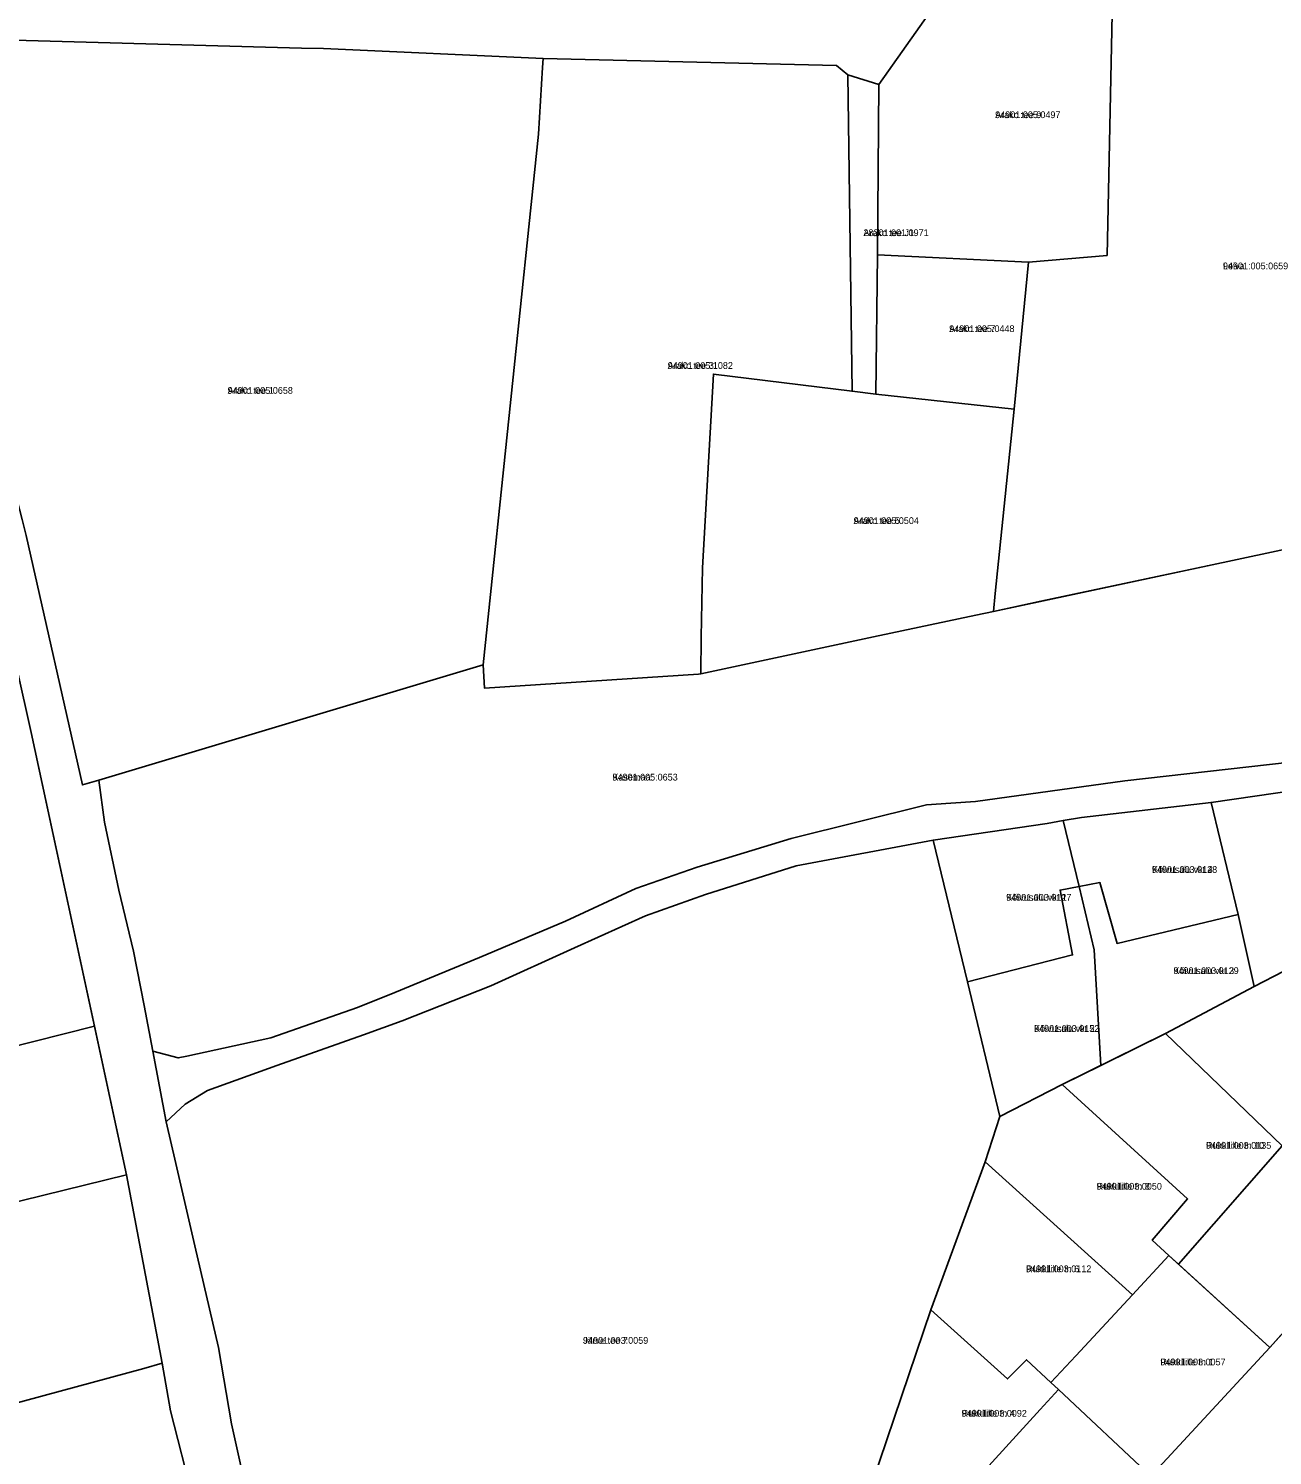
# Model space of a CAD drawing. Extents: x 647845 to 668483, y 6445298 to 6473683.
# Drawn here: x 652826.7 to 653103.1, y 6468125.6 to 6468442.7 of the extents above; entities that cross this region are included whole.
import ezdxf

# ---------------------------------------------------------------- set-up
doc = ezdxf.new("R2010")
doc.units = 0
for name, color, linetype in [('L_AADRESS', 7, 'Continuous'), ('PIIR', 7, 'Continuous'), ('TUNNUS', 7, 'Continuous')]:
    doc.layers.add(name, color=color, linetype=linetype)

msp = doc.modelspace()

# ---------------------------------------------------------------- linework, layer by layer
at = {"layer": 'PIIR'}
for points in [[(653087.15, 6468455.12), (653106.19, 6468452.12), (653126.25, 6468450.45), (653141.05, 6468449.59), (653142.85, 6468409), (653140.61, 6468376.44), (653143.13, 6468374.95), (653143.07, 6468373.88), (653142.39, 6468357.49), (653141.94, 6468346.77), (653141.8, 6468343.37), (653141.18, 6468340.19), (653140.59, 6468337.22), (653138.12, 6468335.41), (653131.32, 6468332.4), (653088.65, 6468323.31), (653051.67, 6468315.43), (653041.08, 6468313.17), (653041.5, 6468317.18), (653045.72, 6468358.09), (653048.9, 6468390.78), (653066.36, 6468392.28), (653067.62, 6468453.16), (653067.74, 6468456.41)], [(653066.36, 6468392.28), (653048.9, 6468390.78), (653015.37, 6468392.4), (653015.66, 6468430.26), (653032.96, 6468454.83), (653067.62, 6468453.16)], [(652810.15, 6468440.46), (652887.33, 6468438.3), (652892.24, 6468438.27), (652941, 6468436.05), (652940.88, 6468434.02), (652940.02, 6468419.18), (652927.71, 6468301.3), (652842.29, 6468275.7), (652838.61, 6468274.61), (652826.09, 6468330.06), (652825.23, 6468333.58), (652811.23, 6468387.58), (652801.01, 6468421.51), (652800.8, 6468423.5), (652803.12, 6468427.72), (652808.72, 6468437.86)], [(653006.24, 6468434.44), (653008.74, 6468432.39), (653009.69, 6468362.1), (652978.88, 6468365.9), (652976.42, 6468322.83), (652976.11, 6468307.47), (652976.04, 6468299.31), (652975.52, 6468299.2), (652928.01, 6468296.08), (652927.71, 6468301.3), (652940.02, 6468419.18), (652940.88, 6468434.02), (652941, 6468436.05)], [(653015.37, 6468392.4), (653015, 6468361.45), (653009.69, 6468362.1), (653008.74, 6468432.39), (653015.66, 6468430.26)], [(653045.72, 6468358.09), (653015, 6468361.45), (653015.37, 6468392.4), (653048.9, 6468390.78)], [(653045.72, 6468358.09), (653041.5, 6468317.18), (653041.08, 6468313.17), (653037.22, 6468312.35), (653014.41, 6468307.49), (653007.19, 6468305.95), (652976.04, 6468299.31), (652976.11, 6468307.47), (652976.42, 6468322.83), (652978.88, 6468365.9), (653009.69, 6468362.1), (653015, 6468361.45)], [(653108.88, 6468273.5), (653117.53, 6468238.89), (653115.2, 6468237.74), (653111.23, 6468236.99), (653105.63, 6468233.25), (653099.07, 6468229.79), (653095.48, 6468245.8), (653089.47, 6468270.74)], [(653060.67, 6468267.37), (653089.47, 6468270.74), (653095.48, 6468245.8), (653068.57, 6468239.41), (653064.76, 6468252.9), (653060.14, 6468252.03), (653056.62, 6468266.7)], [(653053.06, 6468266.06), (653056.62, 6468266.7), (653060.14, 6468252.03), (653055.9, 6468251.23), (653058.7, 6468236.84), (653035.31, 6468230.83), (653027.73, 6468262.36)], [(653159.55, 6468255.25), (653155.18, 6468250.32), (653127.94, 6468219.57), (653105.24, 6468194.42), (653079.36, 6468219.39), (653099.07, 6468229.79), (653105.63, 6468233.25), (653111.23, 6468236.99), (653115.2, 6468237.74), (653117.53, 6468238.89), (653121.97, 6468241.09), (653139.46, 6468249.71), (653149.66, 6468254.73), (653156.84, 6468258.27)], [(653064.76, 6468252.9), (653068.57, 6468239.41), (653095.48, 6468245.8), (653099.07, 6468229.79), (653079.36, 6468219.39), (653064.95, 6468212.29), (653063.48, 6468237.97), (653060.14, 6468252.03)], [(653035.31, 6468230.83), (653058.7, 6468236.84), (653055.9, 6468251.23), (653060.14, 6468252.03), (653063.48, 6468237.97), (653064.95, 6468212.29), (653056.37, 6468208.06), (653042.5, 6468200.92)], [(652708.05, 6468164.62), (652668.02, 6468177.22), (652841.34, 6468221.01), (652848.45, 6468187.96), (652728.2, 6468158.42)], [(653076.39, 6468173.43), (653084.24, 6468182.61), (653056.37, 6468208.06), (653079.36, 6468219.39), (653105.24, 6468194.42), (653082.22, 6468168.12), (653080.11, 6468170.05)], [(653042.5, 6468200.92), (653056.37, 6468208.06), (653084.24, 6468182.61), (653076.39, 6468173.43), (653080.11, 6468170.05), (653071.99, 6468161.31), (653039.28, 6468190.86)], [(653082.22, 6468168.12), (653105.24, 6468194.42), (653125.06, 6468175.07), (653111.91, 6468159.99), (653129.22, 6468144.14), (653132.9, 6468140.76), (653130.64, 6468137.01), (653126.55, 6468140.66), (653108.78, 6468156.49), (653102.5, 6468149.63)], [(653048.46, 6468146.9), (653044.19, 6468142.63), (653027.19, 6468157.96), (653039.28, 6468190.86), (653071.99, 6468161.31), (653059.42, 6468147.77), (653053.89, 6468141.82)], [(652728.2, 6468158.42), (652848.45, 6468187.96), (652856.38, 6468146.12), (652852.26, 6468144.93), (652788.49, 6468127.7), (652750.15, 6468133.39)], [(653059.42, 6468147.77), (653071.99, 6468161.31), (653080.11, 6468170.05), (653102.5, 6468149.63), (653078.78, 6468123.92), (653076.11, 6468121.03), (653055.56, 6468140.26), (653053.89, 6468141.82)], [(653053.89, 6468141.82), (653055.56, 6468140.26), (653051.5, 6468135.82), (653030.87, 6468113.23), (653024.23, 6468106.41), (653012.5, 6468114.64), (653027.19, 6468157.96), (653044.19, 6468142.63), (653048.46, 6468146.9)], [(653108.76, 6468156.54), (653126.5, 6468140.67), (653130.64, 6468137.01), (653119.41, 6468124.87), (653097.41, 6468101.09), (653077.36, 6468119.85), (653076.11, 6468121.03), (653078.78, 6468123.92), (653102.5, 6468149.63)], [(652852.26, 6468144.93), (652856.38, 6468146.12), (652858.19, 6468135.57), (652863.15, 6468116.11), (652866.02, 6468104.67), (652868.33, 6468095.86), (652865.88, 6468090.16), (652831.1, 6468071.11), (652788.49, 6468127.7)], [(653055.56, 6468140.26), (653076.11, 6468121.03), (653077.36, 6468119.85), (653073.77, 6468116.32), (653052.66, 6468093.31), (653030.87, 6468113.23), (653051.5, 6468135.82)]]:
    msp.add_lwpolyline(points, close=True, dxfattribs=at)
for points in [[(653032.96, 6468454.83), (653015.66, 6468430.26), (653008.74, 6468432.39), (653006.24, 6468434.44), (652941, 6468436.05), (652892.24, 6468438.27), (652887.33, 6468438.3), (652810.15, 6468440.46), (652808.72, 6468437.86), (652803.12, 6468427.72), (652800.8, 6468423.5), (652798.4, 6468427.73), (652787.68, 6468441.64), (652775.05, 6468447.96)], [(653134.64, 6468282.77), (653070.29, 6468275.56), (653037.1, 6468270.93), (653031.65, 6468270.55), (653026.19, 6468270.16), (652996.13, 6468262.72), (652975.28, 6468256.34), (652961.66, 6468251.61), (652946, 6468244.36), (652926.86, 6468236.28), (652908.06, 6468228.5), (652899.74, 6468225.18), (652880.47, 6468218.43), (652861.82, 6468214.33), (652859.92, 6468213.96), (652854.28, 6468215.46), (652852.34, 6468225.61), (652849.99, 6468237.71), (652846.69, 6468251.24), (652843.57, 6468266.31), (652842.29, 6468275.7), (652927.71, 6468301.3), (652928.01, 6468296.08), (652975.52, 6468299.2), (652976.04, 6468299.31), (653007.19, 6468305.95), (653014.41, 6468307.49), (653037.22, 6468312.35), (653041.08, 6468313.17), (653088.65, 6468323.31), (653131.32, 6468332.4)], [(652826.09, 6468330.06), (652838.61, 6468274.61), (652842.29, 6468275.7), (652843.57, 6468266.31), (652846.69, 6468251.24), (652849.99, 6468237.71), (652852.34, 6468225.61), (652854.28, 6468215.46), (652857.26, 6468199.76), (652859.4, 6468190.49), (652863.63, 6468172.17), (652868.86, 6468149.63), (652871.74, 6468132.65), (652874.72, 6468119.35)], [(652820.98, 6468314.16), (652827.25, 6468286.23), (652841.34, 6468221.01), (652668.02, 6468177.22)], [(652863.15, 6468116.11), (652858.19, 6468135.57), (652856.38, 6468146.12), (652848.45, 6468187.96), (652827.25, 6468286.23), (652820.98, 6468314.16)], [(653108.88, 6468273.5), (653089.47, 6468270.74), (653060.67, 6468267.37), (653056.62, 6468266.7), (653053.06, 6468266.06), (653027.73, 6468262.36), (652997.29, 6468256.61), (652977.12, 6468250.29), (652963.78, 6468245.54), (652947.96, 6468238.42), (652929.37, 6468229.98), (652909.69, 6468222.2), (652901.13, 6468219.05), (652881.8, 6468212.26), (652866.46, 6468206.75), (652861.44, 6468203.67), (652857.26, 6468199.76), (652854.28, 6468215.46), (652859.92, 6468213.96), (652861.82, 6468214.33), (652880.47, 6468218.43), (652899.74, 6468225.18), (652908.06, 6468228.5), (652926.86, 6468236.28), (652946, 6468244.36), (652961.66, 6468251.61), (652975.28, 6468256.34), (652996.13, 6468262.72), (653026.19, 6468270.16), (653031.65, 6468270.55), (653037.1, 6468270.93), (653070.29, 6468275.56), (653134.64, 6468282.77)], [(652874.72, 6468119.35), (652871.74, 6468132.65), (652868.86, 6468149.63), (652863.63, 6468172.17), (652859.4, 6468190.49), (652857.26, 6468199.76), (652861.44, 6468203.67), (652866.46, 6468206.75), (652881.8, 6468212.26), (652901.13, 6468219.05), (652909.69, 6468222.2), (652929.37, 6468229.98), (652947.96, 6468238.42), (652963.78, 6468245.54), (652977.12, 6468250.29), (652997.29, 6468256.61), (653027.73, 6468262.36), (653035.31, 6468230.83), (653042.5, 6468200.92), (653039.28, 6468190.86), (653027.19, 6468157.96), (653012.5, 6468114.64)]]:
    msp.add_lwpolyline(points, dxfattribs=at)

# ---------------------------------------------------------------- texts
at = {"layer": 'L_AADRESS'}
for s, p in [('Arako tee 9', (653041.49, 6468422.78)), ('Arako tee J1', (653012.2, 6468396.56)), ('Leiva', (653092.11, 6468389.19)), ('Arako tee 7', (653031.28, 6468375.24)), ('Arako tee 3', (652968.7, 6468367.06)), ('Arako tee 1', (652870.9, 6468361.52)), ('Arako tee 5', (653010.03, 6468332.6)), ('Kasemaa', (652956.43, 6468275.59)), ('Kõivusalu vkt 4', (653076.33, 6468255.07)), ('Kõivusalu vkt 1', (653043.93, 6468248.89)), ('Kõivusalu vkt 3', (653081.11, 6468232.59)), ('Kõivusalu vkt 2', (653050.13, 6468219.74)), ('Rukkilille tn 10', (653088.35, 6468193.76)), ('Rukkilille tn 8', (653064.04, 6468184.68)), ('Rukkilille tn 6', (653048.35, 6468166.34)), ('Järve tee 7', (652949.88, 6468150.43)), ('Rukkilille tn 1', (653078.2, 6468145.64)), ('Rukkilille tn 4', (653034.03, 6468134.24))]:
    msp.add_text(s, height=1.5, dxfattribs=at).set_placement(p)
at = {"layer": 'TUNNUS'}
for s, p in [('94901:005:0497', (653041.49, 6468422.78)), ('28301:001:0971', (653012.2, 6468396.56)), ('94901:005:0659', (653092.11, 6468389.19)), ('94901:005:0448', (653031.28, 6468375.24)), ('94901:005:1082', (652968.7, 6468367.06)), ('94901:005:0658', (652870.9, 6468361.52)), ('94901:005:0504', (653010.03, 6468332.6)), ('94901:005:0653', (652956.43, 6468275.59)), ('94901:003:0128', (653076.33, 6468255.07)), ('94901:003:0127', (653043.93, 6468248.89)), ('94901:003:0129', (653081.11, 6468232.59)), ('94901:003:0152', (653050.13, 6468219.74)), ('94901:003:0135', (653088.35, 6468193.76)), ('94901:003:0050', (653064.04, 6468184.68)), ('94901:003:0112', (653048.35, 6468166.34)), ('94901:003:0059', (652949.88, 6468150.43)), ('94901:003:0057', (653078.2, 6468145.64)), ('94901:003:0092', (653034.03, 6468134.24))]:
    msp.add_text(s, height=1.5, dxfattribs=at).set_placement(p)

doc.saveas('drawing.dxf')
